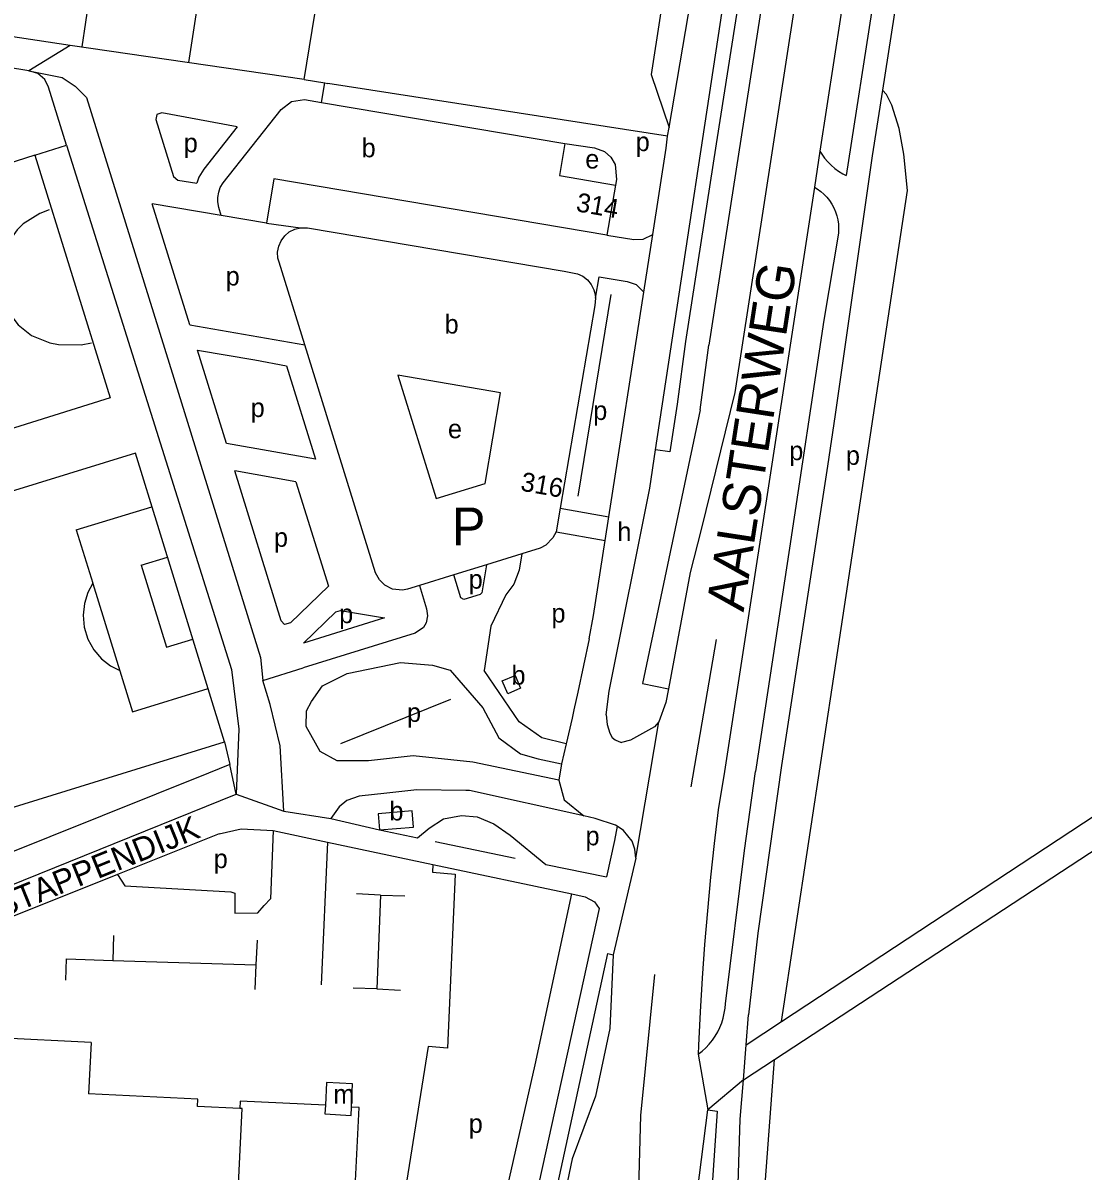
# Model space of a CAD drawing. Extents: x 161093 to 163177, y 379000 to 380904.
# Drawn here: x 161396.9 to 161621, y 379727.5 to 379970.4 of the extents above; entities that cross this region are included whole.
import ezdxf

# ---------------------------------------------------------------- set-up
doc = ezdxf.new("R2010")
doc.units = 0
for name, color, linetype in [('BLT_Basislijn', 7, 'Continuous'), ('BLT_Bebouwing', 7, 'Continuous'), ('BLT_Centroide', 7, 'Continuous'), ('BLT_Huisnummer', 7, 'Continuous'), ('BLT_Huisnummer_zonder_bebouwing', 7, 'Continuous'), ('BLT_Onderdoorgang_en_onderverdeling', 7, 'Continuous'), ('BLT_Straatnaam', 7, 'Continuous'), ('BLT_Straatnaam_hoofdweg', 7, 'Continuous'), ('BLT_Tekst_parkeren', 7, 'Continuous'), ('BLT_Vlakafsluiter', 7, 'Continuous')]:
    doc.layers.add(name, color=color, linetype=linetype)

msp = doc.modelspace()

# ---------------------------------------------------------------- linework, layer by layer
at = {"layer": 'BLT_Basislijn'}
for p, q in [((161409.36, 379965.29), (161418.47, 380024.73)), ((161431.97, 379962.01), (161441.06, 380021.29)), ((161456.32, 379958.37), (161466.04, 380017.55)), ((161582.09, 380009.64), (161570.95, 379938.07)), ((161586.83, 380009.21), (161578.64, 379956.17)), ((161550.39, 379989.11), (161543.47, 379944.8)), ((161555.33, 379988.35), (161541.89, 379902.19)), ((161406.84, 379965.63), (161376.95, 379970.02)), ((161456.32, 379958.37), (161406.84, 379965.63)), ((161456.32, 379958.37), (161460.7, 379957.67)), ((161460.01, 379953.57), (161460.7, 379957.67)), ((161460.7, 379957.67), (161461.33, 379957.57)), ((161533.18, 379946.4), (161461.33, 379957.57)), ((161578.64, 379956.17), (161576.49, 379942.27)), ((161532.9, 379943.89), (161533.18, 379946.4)), ((161399.36, 379942.38), (161406.1, 379944.52)), ((161406.1, 379944.52), (161440.97, 379833.57)), ((161530.06, 379925.65), (161532.9, 379943.89)), ((161543.47, 379944.8), (161536.95, 379902.96)), ((161399.36, 379942.38), (161312.14, 379914.6)), ((161399.36, 379942.38), (161415.33, 379891.05)), ((161438.8, 379929.64), (161424.2, 379932.11)), ((161432.13, 379906.5), (161424.2, 379932.11)), ((161448.37, 379928.04), (161455.58, 379927.01)), ((161528.17, 379913.43), (161530.06, 379925.65)), ((161514.27, 379870.28), (161521.25, 379912.89)), ((161520.78, 379865.88), (161528.17, 379913.43)), ((161432.13, 379906.5), (161456.49, 379902.28)), ((161557.29, 379759.15), (161778.66, 379904.88)), ((161536.95, 379902.96), (161535.23, 379889.74)), ((161540.07, 379888.51), (161541.89, 379902.19)), ((161439.9, 379881.42), (161433.79, 379901.15)), ((161452.63, 379897.85), (161458.75, 379878.1)), ((161415.33, 379891.05), (161327.93, 379863.85)), ((161458.75, 379878.1), (161439.9, 379881.42)), ((161454.58, 379873.32), (161441.7, 379875.59)), ((161567.02, 379876.62), (161557.26, 379813.28)), ((161408.15, 379863.11), (161424.11, 379868.04)), ((161510.48, 379867.7), (161520.78, 379865.88)), ((161520, 379860.91), (161520.78, 379865.88)), ((161408.15, 379863.11), (161411.62, 379851.86)), ((161509.63, 379862.74), (161520, 379860.91)), ((161540.31, 379863.23), (161538, 379854.1)), ((161517.53, 379845), (161520, 379860.91)), ((161558.97, 379859.26), (161551.8, 379811.99)), ((161421.88, 379855.66), (161427.42, 379857.37)), ((161421.88, 379855.66), (161427.24, 379838.31)), ((161538, 379854.1), (161533.38, 379829.51)), ((161411.64, 379851.81), (161420.02, 379824.65)), ((161473.34, 379844.52), (161456.2, 379839.18)), ((161516.59, 379840.06), (161517.53, 379845)), ((161479.8, 379841.3), (161456.12, 379833.92)), ((161427.24, 379838.31), (161432.78, 379840.02)), ((161543.44, 379839.94), (161538.14, 379808.8)), ((161420.02, 379824.65), (161436.01, 379829.59)), ((161520.22, 379824.01), (161520.82, 379828.98)), ((161533.38, 379829.51), (161532.83, 379826.6)), ((161464.09, 379817.94), (161487.35, 379827.32)), ((161439.51, 379818.27), (161440.6, 379813.51)), ((161440.6, 379813.51), (161436.11, 379811.7)), ((161510.18, 379810.19), (161491.98, 379814.01)), ((161510.76, 379813.66), (161510.18, 379810.19)), ((161452.02, 379803.6), (161462, 379802.05)), ((161462, 379802.05), (161472.24, 379799.65)), ((161472.24, 379799.65), (161480.3, 379797.98)), ((161555.8, 379751.1), (161631.7, 379800.84)), ((161461.3, 379797.07), (161459.96, 379766.89)), ((161484.03, 379797.21), (161500.97, 379793.7)), ((161472.49, 379785.87), (161467.38, 379786.14)), ((161472.49, 379785.87), (161471.69, 379766.01)), ((161472.49, 379785.87), (161477.65, 379785.69)), ((161518.74, 379783.05), (161501.53, 379704.6)), ((161416.04, 379777.32), (161415.87, 379772.07)), ((161446.4, 379776.34), (161446.15, 379771.11)), ((161446.15, 379771.11), (161445.9, 379765.88)), ((161471.69, 379766.01), (161466.68, 379766.17)), ((161471.69, 379766.01), (161476.71, 379765.78)), ((161549.8, 379754.23), (161550.29, 379760.56)), ((161549.8, 379754.23), (161557.29, 379759.15)), ((161549.22, 379746.79), (161549.8, 379754.23)), ((161549.22, 379746.79), (161555.8, 379751.1)), ((161553.92, 379725.65), (161555.8, 379751.1))]:
    msp.add_line(p, q, dxfattribs=at)
for points in [[(161614.79, 380263.11), (161612.25, 380247.81), (161591.56, 380113.29), (161571.33, 379981.65), (161565.42, 379943.25)], [(161530.67, 379880.09), (161547.5, 379990.95), (161552.15, 380025.02), (161565.2, 380110.38), (161569.19, 380135.98)], [(161533.5, 379948.27), (161540.99, 379992.26), (161545.37, 380024.52), (161555.56, 380091.1), (161562.65, 380136.96)], [(161584.58, 380133.67), (161561.44, 379983.17), (161547.44, 379892.21), (161540.31, 379863.23)], [(161537.02, 380007.07), (161529.73, 379959.44), (161533.5, 379948.27)], [(161398.13, 379960.25), (161393.42, 379961.03), (161358.28, 379964.54), (161351.39, 379957.38)], [(161406.1, 379944.52), (161402.28, 379956.79), (161401.49, 379958.37), (161400.03, 379959.65), (161398.13, 379960.25)], [(161398.13, 379960.25), (161405.17, 379958.84), (161407.93, 379956.99), (161410.28, 379954.59), (161429.77, 379892.02)], [(161557.29, 379759.15), (161568.83, 379835.28), (161583.94, 379934.95), (161583.12, 379942.62), (161582.14, 379948.01), (161580.63, 379952.95), (161579.5, 379955.24), (161578.64, 379956.17)], [(161442.19, 379948.39), (161426.24, 379951.37), (161425.19, 379951.01), (161424.94, 379949.91), (161428.69, 379937.88), (161429.61, 379937.12), (161433.61, 379936.45)], [(161442.19, 379948.39), (161435.14, 379939.42), (161434.09, 379937.75), (161433.61, 379936.45)], [(161533.18, 379946.4), (161533.5, 379948.27)], [(161511.48, 379944.9), (161517.76, 379943.95), (161519.83, 379943.16), (161521.18, 379941.96), (161522.08, 379940.4), (161522.36, 379937.27), (161522.17, 379936.06)], [(161565.42, 379943.25), (161564.24, 379935.62)], [(161565.42, 379943.25), (161565.8, 379942.61), (161566.4, 379941.78), (161567.05, 379941), (161567.77, 379940.27), (161568.54, 379939.6), (161569.36, 379939), (161570.23, 379938.46), (161570.95, 379938.07)], [(161576.49, 379942.27), (161568.6, 379887.54), (161567.02, 379876.62)], [(161564.24, 379935.62), (161545.22, 379812.05)], [(161564.24, 379935.62), (161564.85, 379935.25), (161565.57, 379934.72), (161566.25, 379934.13), (161566.87, 379933.48), (161567.43, 379932.78), (161567.93, 379932.03), (161568.35, 379931.24), (161568.71, 379930.42), (161568.99, 379929.57), (161569.19, 379928.69), (161569.32, 379927.8), (161569.36, 379926.91), (161569.33, 379926.01), (161569.32, 379925.9)], [(161402.44, 379930.85), (161400.45, 379930.03), (161396.9, 379927.85), (161395.63, 379926.62), (161393.31, 379923.33), (161392.37, 379921.15), (161391.69, 379918.11), (161392, 379913.4), (161393.69, 379909.38), (161395.87, 379906.54), (161398.68, 379904.27), (161402.58, 379902.7), (161404.39, 379902.34), (161409.18, 379902.25), (161411.39, 379902.67)], [(161569.32, 379925.9), (161566.22, 379907.52), (161558.97, 379859.26)], [(161520.33, 379925.47), (161526.06, 379924.58), (161528.06, 379924.61), (161530.06, 379925.65)], [(161517.95, 379912.15), (161518.75, 379916.65), (161524.62, 379915.7), (161526.54, 379915.06), (161528.17, 379913.43)], [(161433.79, 379901.15), (161445.88, 379899.11), (161452.63, 379897.85)], [(161429.77, 379892.02), (161447.1, 379836.15), (161447.58, 379831.26)], [(161535.23, 379889.74), (161533.65, 379879.63), (161530.67, 379880.09)], [(161540.07, 379888.51), (161527.9, 379830.66), (161533.38, 379829.51)], [(161529.44, 379871.98), (161530.67, 379880.09)], [(161420.64, 379879.36), (161328.97, 379851.05)], [(161425.65, 379863.14), (161420.64, 379879.36)], [(161454.58, 379873.32), (161461.49, 379851.22), (161453.43, 379843.46), (161452.21, 379843.14), (161451.51, 379843.91), (161441.7, 379875.59)], [(161520.82, 379828.98), (161529.44, 379871.98)], [(161439.51, 379818.27), (161425.65, 379863.14)], [(161502.38, 379858.08), (161501.79, 379854.6), (161500.67, 379851.66), (161498.97, 379849.38), (161495.79, 379842.75), (161494.38, 379833.39)], [(161494.93, 379855.76), (161493.93, 379849.84), (161493.55, 379849.43), (161490.1, 379848.39), (161489.48, 379848.76), (161487.99, 379853.6)], [(161328.97, 379851.05), (161347.84, 379789.96), (161439.51, 379818.27)], [(161411.63, 379851.84), (161410.59, 379849.86), (161409.88, 379847.59), (161409.61, 379845.1), (161409.85, 379842.53), (161410.62, 379840.04), (161411.87, 379837.78), (161413.5, 379835.88), (161415.36, 379834.4), (161417.33, 379833.36)], [(161480.73, 379851.35), (161482.24, 379846.4), (161482.43, 379844.93), (161482.11, 379843.49), (161481.55, 379842.49), (161479.8, 379841.3)], [(161456.2, 379839.18), (161463.06, 379845.79), (161464.05, 379846.09), (161473.34, 379844.52)], [(161516.59, 379840.06), (161514.2, 379828.83)], [(161440.97, 379833.57), (161442.49, 379820.99), (161441.93, 379807.22)], [(161447.58, 379831.26), (161456.12, 379833.92)], [(161469.98, 379814.3), (161463.32, 379814.3), (161459.74, 379816.22), (161456.73, 379821.51), (161456.83, 379824.85), (161457.88, 379826.8), (161460.22, 379830.12), (161465.43, 379832.77), (161476.71, 379835.06), (161483.49, 379834.53), (161487.24, 379833.48), (161494.09, 379825.5), (161497.48, 379819.15), (161502.08, 379815.77), (161505.8, 379814.67), (161510.76, 379813.66)], [(161452.02, 379803.6), (161451.29, 379817.43), (161449.14, 379826.22), (161447.58, 379831.26)], [(161511.77, 379817.9), (161506.63, 379819.12), (161501.82, 379822.54), (161494.38, 379833.39)], [(161514.2, 379828.83), (161513.4, 379825.05), (161513, 379823.32)], [(161532.83, 379826.6), (161531.36, 379822.55)], [(161520.22, 379824.01), (161520.42, 379821.96), (161520.98, 379820.11), (161521.5, 379819.24), (161522.14, 379818.72), (161522.91, 379818.34), (161523.48, 379818.18)], [(161513, 379823.32), (161511.77, 379817.9)], [(161531.36, 379822.55), (161530.41, 379821.44), (161525.34, 379818.66)], [(161525.34, 379818.66), (161523.48, 379818.18)], [(161491.98, 379814.01), (161479.39, 379815.35), (161469.98, 379814.3)], [(161436.11, 379811.7), (161323.99, 379766.68), (161308.57, 379761.81), (161221.63, 379741.24)], [(161441.93, 379807.22), (161440.6, 379813.51)], [(161545.22, 379812.05), (161543.86, 379803.89), (161543.03, 379796.79), (161542.29, 379789.68), (161541.62, 379782.56), (161541.03, 379775.43), (161540.52, 379768.3), (161540.09, 379761.17), (161539.74, 379754.03), (161539.67, 379752.23)], [(161545.41, 379762.86), (161549.43, 379795.32), (161551.8, 379811.99)], [(161557.26, 379813.28), (161552.3, 379777.8), (161550.29, 379760.56)], [(161208.76, 379732.54), (161301.74, 379754.18), (161325.58, 379760.47), (161336.07, 379764.44), (161441.93, 379807.22)], [(161473.8, 379807.44), (161467.99, 379806.8), (161465.35, 379805.88), (161463.76, 379804.52), (161462, 379802.05)], [(161490.56, 379808.03), (161480.18, 379808.14), (161473.8, 379807.44)], [(161515.45, 379802.66), (161491.29, 379808.02), (161490.56, 379808.03)], [(161480.3, 379797.98), (161482.79, 379800.05), (161485.84, 379801.97), (161489.58, 379802.68), (161492.92, 379802.43), (161496.42, 379800.96), (161499.93, 379798.57), (161507.42, 379792.36), (161520.25, 379789.71)], [(161522.51, 379800.43), (161522.15, 379800.67), (161517.91, 379802.11), (161515.45, 379802.66)], [(161438.34, 379798.8), (161443.04, 379799.86), (161449.8, 379799.52)], [(161449.8, 379799.52), (161449.23, 379785.1)], [(161449.8, 379799.52), (161461.3, 379797.07)], [(161522.51, 379800.43), (161521.98, 379797.43), (161520.25, 379789.71)], [(161526.48, 379793.67), (161526.27, 379795.57), (161525.69, 379797.26), (161523.89, 379799.51), (161522.51, 379800.43)], [(161438.34, 379798.8), (161416.88, 379790.23)], [(161461.3, 379797.07), (161483.55, 379792.35)], [(161483.55, 379792.35), (161483.45, 379790.75), (161488.3, 379790.29)], [(161483.55, 379792.35), (161512.95, 379786.11)], [(161526.48, 379793.67), (161521.69, 379773.24)], [(161416.88, 379790.23), (161344.77, 379761.38), (161325.92, 379754.48), (161313.75, 379751.03), (161221.98, 379730.11)], [(161416.88, 379790.23), (161418.44, 379787.85), (161440.81, 379786.57), (161441.68, 379786.27), (161441.68, 379782.04), (161446.52, 379782.09), (161447.89, 379783.64), (161449.23, 379785.1)], [(161488.3, 379790.29), (161486.64, 379753.46), (161482.53, 379753.86), (161477.22, 379720.29), (161471.35, 379680.39)], [(161455.37, 379656.3), (161472.95, 379656.33), (161486.26, 379666.23), (161491.43, 379689.22), (161505.18, 379750), (161512.95, 379786.11)], [(161512.95, 379786.11), (161515.77, 379785.52), (161517.76, 379784.43), (161518.74, 379783.05)], [(161495.14, 379653.36), (161495.28, 379654.68), (161496.1, 379659.5), (161497.02, 379664.64), (161497.9, 379669.23), (161520.53, 379773.49), (161521.69, 379773.24)], [(161521.69, 379773.24), (161520.98, 379757.67), (161517.98, 379743.34), (161513.02, 379730.07), (161507.19, 379702.12), (161502.15, 379673.31)], [(161405.95, 379767.9), (161406.09, 379772.38), (161415.87, 379772.07)], [(161415.87, 379772.07), (161446.15, 379771.11)], [(161526.81, 379713.54), (161527.57, 379739.24), (161530.47, 379769.11)], [(161539.67, 379752.23), (161540.5, 379752.88), (161541.28, 379753.58), (161542, 379754.34), (161542.66, 379755.16), (161543.26, 379756.02), (161543.79, 379756.93), (161544.25, 379757.88), (161544.64, 379758.85), (161544.95, 379759.86), (161545.18, 379760.88), (161545.34, 379761.92), (161545.41, 379762.86)], [(161546.71, 379678.82), (161548.57, 379738.44), (161549.22, 379746.79)], [(161533.29, 379672.54), (161536.36, 379698.44), (161541.68, 379740.45)], [(161541.68, 379740.45), (161543.69, 379740.16), (161542.27, 379719.34), (161541.65, 379702.77), (161541.15, 379680.49), (161541.3, 379677.1)]]:
    msp.add_lwpolyline(points, dxfattribs=at)
at = {"layer": 'BLT_Bebouwing'}
for p, q in [((161460.01, 379953.57), (161511.48, 379944.9)), ((161522.17, 379936.06), (161520.33, 379925.47)), ((161448.37, 379928.04), (161438.8, 379929.64)), ((161497.88, 379892.15), (161476.12, 379895.85)), ((161510.48, 379867.7), (161509.63, 379862.74)), ((161502.38, 379858.08), (161494.93, 379855.76)), ((161494.93, 379855.76), (161487.99, 379853.6)), ((161487.99, 379853.6), (161480.73, 379851.35)), ((161411.28, 379754.68), (161386.87, 379755.87)), ((161411.28, 379754.68), (161410.74, 379743.81)), ((161466.38, 379741.02), (161466.57, 379745.93)), ((161442.71, 379740.73), (161433.81, 379741.18))]:
    msp.add_line(p, q, dxfattribs=at)
for points in [[(161438.8, 379929.64), (161438.26, 379931.34), (161438.06, 379932.49), (161438.05, 379933.45), (161438.26, 379934.59), (161438.6, 379935.54), (161439.23, 379936.54), (161451.45, 379952.09), (161453.68, 379953.77), (161456.44, 379954.17), (161460.01, 379953.57)], [(161511.48, 379944.9), (161510.34, 379938.12), (161522.17, 379936.06)], [(161520.33, 379925.47), (161449.95, 379937.37), (161448.37, 379928.04)], [(161456.49, 379902.28), (161451.07, 379919.74), (161450.8, 379920.62), (161450.73, 379921.89), (161450.96, 379923.14), (161451.49, 379924.29), (161452.23, 379925.32), (161453.2, 379926.16), (161454.34, 379926.72), (161455.58, 379927.01)], [(161455.58, 379927.01), (161457.05, 379927.01), (161511.31, 379917.85), (161514.14, 379917.32), (161515.27, 379916.79), (161516.26, 379916.02), (161517.05, 379915.04), (161517.59, 379913.91), (161517.88, 379912.92), (161517.95, 379912.15)], [(161517.95, 379912.15), (161517.78, 379910.61), (161510.48, 379867.7)], [(161480.73, 379851.35), (161478.22, 379850.58), (161477.15, 379850.38), (161475.04, 379850.58), (161473.41, 379851.46), (161472.29, 379852.55), (161471.44, 379854.05), (161456.49, 379902.28)], [(161476.12, 379895.85), (161484.26, 379869.74), (161494.62, 379872.97), (161497.88, 379892.15)], [(161509.63, 379862.74), (161508.96, 379861.43), (161507.45, 379859.92), (161506.22, 379859.28), (161502.38, 379858.08)], [(161479.44, 379800.25), (161479.16, 379803.68), (161471.96, 379803.09)], [(161471.96, 379803.09), (161472.24, 379799.65)], [(161472.24, 379799.65), (161479.44, 379800.25)], [(161466.57, 379745.93), (161461.05, 379746.22), (161460.82, 379741.4)], [(161433.81, 379741.18), (161433.86, 379742.7), (161410.74, 379743.81)], [(161460.82, 379741.4), (161442.79, 379742.29), (161442.71, 379740.73)], [(161441.93, 379695.52), (161465.67, 379694.42), (161467.94, 379740.95), (161466.38, 379741.02)]]:
    msp.add_lwpolyline(points, dxfattribs=at)
msp.add_lwpolyline([(161498.2, 379831.19), (161500.96, 379832.3), (161502.11, 379829.67), (161499.4, 379828.48)], close=True, dxfattribs=at)
at = {"layer": 'BLT_Onderdoorgang_en_onderverdeling'}
for points in [[(161460.82, 379741.4), (161460.73, 379739.6), (161466.28, 379739.28), (161466.38, 379741.02)], [(161441.02, 379695.56), (161443.22, 379740.71), (161442.71, 379740.73)]]:
    msp.add_lwpolyline(points, dxfattribs=at)
at = {"layer": 'BLT_Vlakafsluiter'}
for p, q in [((161406.84, 379965.63), (161398.13, 379960.25)), ((161526.48, 379793.67), (161531.36, 379822.55)), ((161511.77, 379817.9), (161510.76, 379813.66)), ((161441.93, 379807.22), (161452.02, 379803.6)), ((161539.67, 379752.23), (161541.68, 379740.45)), ((161549.22, 379746.79), (161541.68, 379740.45))]:
    msp.add_line(p, q, dxfattribs=at)
msp.add_lwpolyline([(161510.18, 379810.19), (161511.35, 379805.99), (161515.45, 379802.66)], dxfattribs=at)

# ---------------------------------------------------------------- texts
at = {"layer": 'BLT_Centroide'}
for s, p in [('p', (161430.87, 379943.01)), ('b', (161468.49, 379941.95)), ('p', (161526.45, 379943.25)), ('e', (161515.79, 379939.57)), ('p', (161439.74, 379914.82)), ('b', (161486.04, 379904.66)), ('p', (161445.03, 379887)), ('p', (161517.47, 379886.38)), ('e', (161486.75, 379882.51)), ('p', (161558.92, 379877.87)), ('p', (161570.9, 379876.89)), ('p', (161449.95, 379859.55)), ('h', (161522.57, 379860.76)), ('p', (161491.13, 379850.69)), ('p', (161463.74, 379843.4)), ('p', (161508.64, 379843.52)), ('b', (161500.18, 379830.39)), ('p', (161478.09, 379822.51)), ('b', (161474.37, 379801.66)), ('p', (161515.84, 379796.4)), ('p', (161437.21, 379791.58)), ('m', (161462.52, 379741.77)), ('p', (161491.14, 379735.56))]:
    msp.add_text(s, height=4, dxfattribs=at).set_placement(p)
at = {"layer": 'BLT_Huisnummer'}
msp.add_text('314', height=4, rotation=350, dxfattribs=at).set_placement((161513.67, 379930.56))
at = {"layer": 'BLT_Huisnummer_zonder_bebouwing'}
msp.add_text('316', height=4, rotation=350, dxfattribs=at).set_placement((161501.92, 379871.47))
at = {"layer": 'BLT_Straatnaam'}
msp.add_text('STAPPENDIJK', height=5, rotation=22.0842, dxfattribs=at).set_placement((161392.35, 379780.98))
at = {"layer": 'BLT_Straatnaam_hoofdweg'}
msp.add_text('AALSTERWEG', height=8, rotation=81.2709, dxfattribs=at).set_placement((161549.26, 379845.63))
at = {"layer": 'BLT_Tekst_parkeren'}
msp.add_text('P', height=8, dxfattribs=at).set_placement((161487.55, 379859.86))

doc.saveas('drawing.dxf')
